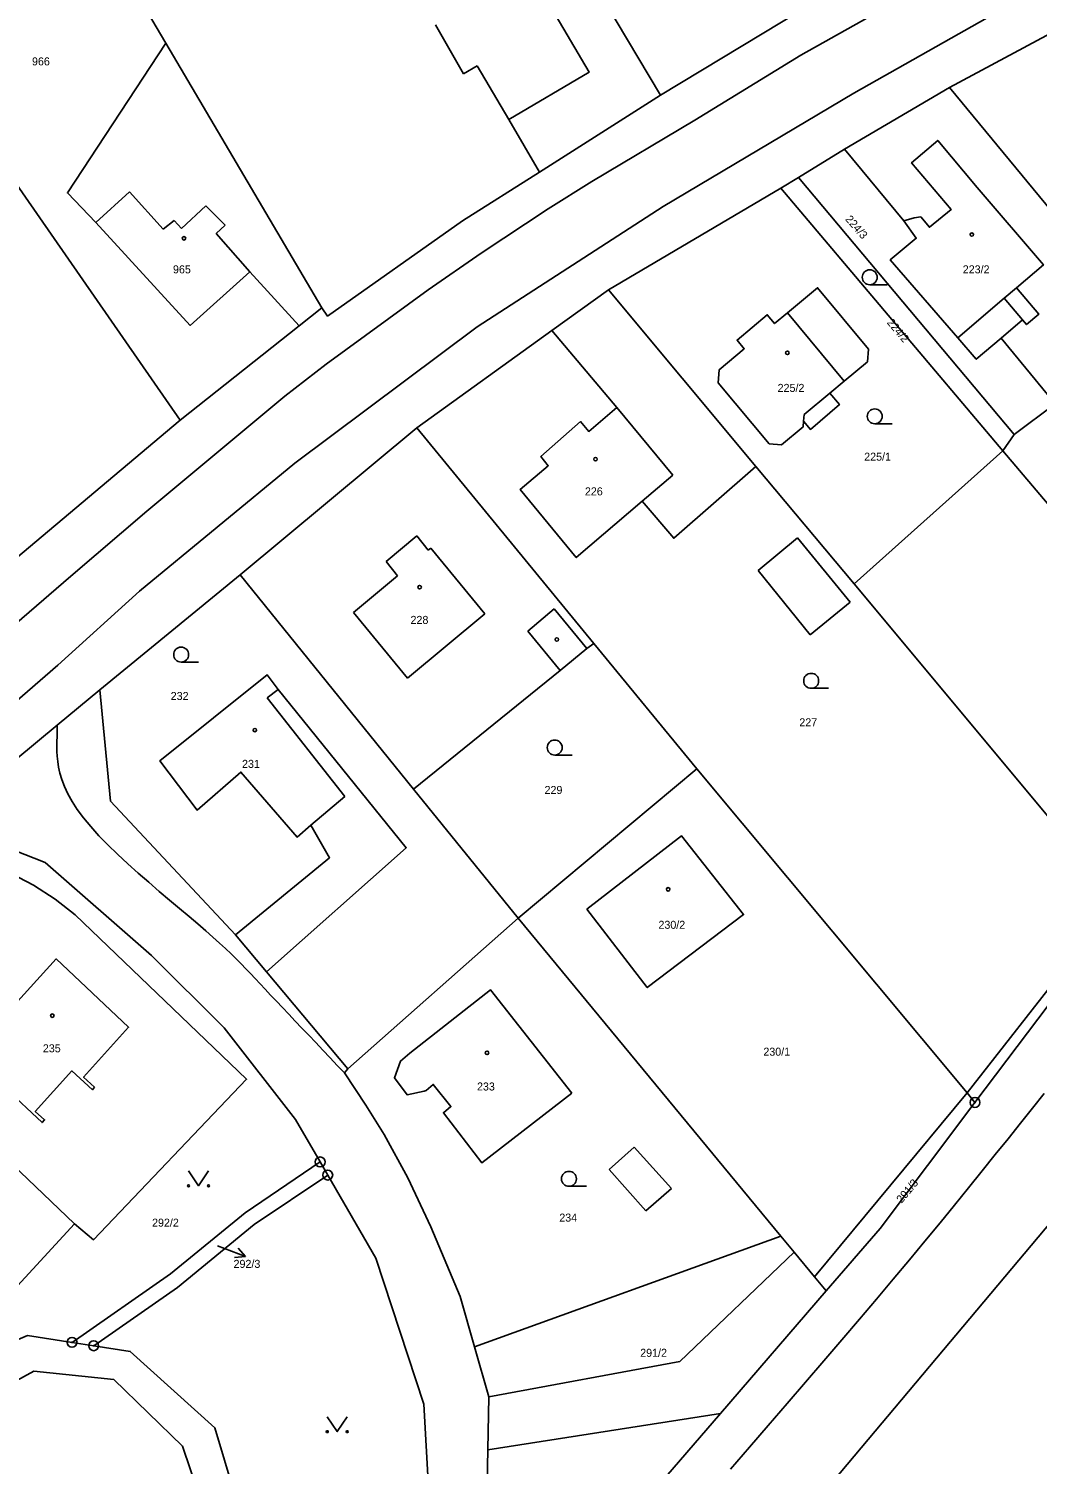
# Model space of a CAD drawing. Extents: x -587171 to -555306, y -1167727 to -1074732.
# Drawn here: x -560131.8 to -560030.6, y -1077699.8 to -1077555.8 of the extents above; entities that cross this region are included whole.
import ezdxf

# ---------------------------------------------------------------- set-up
doc = ezdxf.new("R2010")
doc.units = 0
for name, color, linetype in [('Hranice parcel', 7, 'Continuous'), ('Parcelní čísla', 7, 'Continuous'), ('Pop  PČ popisy', 7, 'Continuous'), ('Poz předměty', 7, 'Continuous'), ('Vnitřní kresba', 7, 'Continuous'), ('Značky bodu BP', 7, 'Continuous'), ('Značky budov', 7, 'Continuous'), ('Značky kultur', 7, 'Continuous')]:
    doc.layers.add(name, color=color, linetype=linetype)

msp = doc.modelspace()

# ---------------------------------------------------------------- linework, layer by layer
at = {"layer": 'Hranice parcel'}
for p, q in [((-560068.43, -1077562.5), (-560040.99, -1077545.9)), ((-560025.67, -1077554.33), (-560039.43, -1077561.72)), ((-560102.42, -1077583.81), (-560118.06, -1077557.27)), ((-560039.43, -1077561.72), (-560049.96, -1077567.9)), ((-560039.43, -1077561.72), (-559998.7, -1077611.06)), ((-560080.58, -1077570.2), (-560068.43, -1077562.5)), ((-560116.63, -1077595.08), (-560137.85, -1077564.54)), ((-560049.96, -1077567.9), (-560054.59, -1077570.74)), ((-560049.96, -1077567.9), (-560044, -1077575.1)), ((-560054.59, -1077570.74), (-560056.35, -1077571.83)), ((-560032.92, -1077596.51), (-560054.59, -1077570.74)), ((-560056.35, -1077571.83), (-560073.65, -1077582.01)), ((-560056.35, -1077571.83), (-560034.06, -1077598.15)), ((-560073.65, -1077582.01), (-560079.33, -1077586.1)), ((-560073.65, -1077582.01), (-560058.85, -1077599.73)), ((-560104.69, -1077585.61), (-560102.42, -1077583.81)), ((-560116.63, -1077595.08), (-560104.69, -1077585.61)), ((-560079.33, -1077586.1), (-560092.89, -1077595.86)), ((-560034.25, -1077586.86), (-560028.8, -1077593.44)), ((-560032.92, -1077596.51), (-560028.8, -1077593.44)), ((-560142.63, -1077616.94), (-560116.63, -1077595.08)), ((-560092.89, -1077595.86), (-560110.62, -1077610.59)), ((-560092.89, -1077595.86), (-560075.1, -1077617.48)), ((-560034.06, -1077598.15), (-560032.92, -1077596.51)), ((-560034.06, -1077598.15), (-560049, -1077611.51)), ((-560010.14, -1077626.51), (-560034.06, -1077598.15)), ((-560058.85, -1077599.73), (-560049, -1077611.51)), ((-560110.62, -1077610.59), (-560124.7, -1077622.14)), ((-560110.62, -1077610.59), (-560093.21, -1077632.08)), ((-560049, -1077611.51), (-560022.53, -1077643.23)), ((-560075.1, -1077617.48), (-560064.76, -1077630.06)), ((-560082.71, -1077645.04), (-560064.76, -1077630.06)), ((-560064.76, -1077630.06), (-560037.66, -1077662.56)), ((-560093.21, -1077632.08), (-560082.71, -1077645.04)), ((-560037.66, -1077662.56), (-560022.53, -1077643.23)), ((-560099.81, -1077660.14), (-560082.71, -1077645.04)), ((-560082.71, -1077645.04), (-560056.35, -1077676.93)), ((-560111.06, -1077646.69), (-560107.95, -1077650.41)), ((-560107.95, -1077650.41), (-560099.81, -1077660.14)), ((-560145.1, -1077658.65), (-560127.22, -1077675.7)), ((-560052.96, -1077681.02), (-560037.66, -1077662.56)), ((-560036.86, -1077663.52), (-560037.66, -1077662.56)), ((-560102.58, -1077669.49), (-560101.82, -1077670.8)), ((-560133.32, -1077682.3), (-560127.22, -1077675.7)), ((-560087.08, -1077688.03), (-560056.35, -1077676.93)), ((-560051.8, -1077682.42), (-560052.96, -1077681.02)), ((-560062.4, -1077694.71), (-560051.8, -1077682.42)), ((-560125.31, -1077687.92), (-560127.48, -1077687.58)), ((-560085.75, -1077698.36), (-560062.4, -1077694.71))]:
    msp.add_line(p, q, dxfattribs=at)
for points in [[(-560068.43, -1077562.5), (-560080.62, -1077541.99), (-560085.27, -1077534.33), (-560093.56, -1077520.46), (-560095.9, -1077516.24)], [(-560080.58, -1077570.2), (-560083.64, -1077564.92), (-560075.59, -1077560.19), (-560086.29, -1077541.98), (-560089.32, -1077543.8), (-560101.87, -1077525.59), (-560106.15, -1077527.99), (-560127.79, -1077540.53)], [(-560118.06, -1077557.27), (-560123.14, -1077548.66), (-560127.79, -1077540.53)], [(-560145.28, -1077619.37), (-560144.61, -1077619.87), (-560143.23, -1077620.49), (-560141.2, -1077620.74), (-560139.18, -1077620.34), (-560137.48, -1077619.22), (-560127.59, -1077610.74), (-560119.96, -1077604.22), (-560106.13, -1077592.68), (-560101.97, -1077589.46), (-560091.75, -1077582.02), (-560086.42, -1077578.33), (-560079.69, -1077573.89), (-560075.31, -1077571.16), (-560064.99, -1077565), (-560054.33, -1077558.48), (-560045.19, -1077553.35), (-560038.88, -1077549.66), (-560028.99, -1077543.83)], [(-560118.06, -1077557.27), (-560127.95, -1077572.29), (-560125.08, -1077575.25), (-560115.64, -1077585.58), (-560109.63, -1077580.21), (-560104.69, -1077585.61)], [(-560044, -1077575.1), (-560042.96, -1077574.79), (-560042.3, -1077574.7), (-560041.44, -1077575.74), (-560039.25, -1077573.95), (-560043.23, -1077569.27), (-560040.6, -1077567.03), (-560036.64, -1077571.74), (-560029.99, -1077579.52), (-560032.7, -1077581.82), (-560030.46, -1077584.46), (-560031.68, -1077585.49), (-560032.08, -1077585.02), (-560034.25, -1077586.86)], [(-560102.42, -1077583.81), (-560101.84, -1077584.65), (-560088.28, -1077575.08), (-560080.58, -1077570.2)], [(-560044, -1077575.1), (-560042.75, -1077576.83), (-560045.37, -1077579.01), (-560038.58, -1077586.81), (-560036.74, -1077588.98), (-560034.25, -1077586.86)], [(-560057.53, -1077597.45), (-560062.62, -1077591.34), (-560062.53, -1077590.02), (-560060.01, -1077587.92), (-560060.73, -1077587.06), (-560057.71, -1077584.51), (-560056.97, -1077585.4), (-560055.69, -1077584.33), (-560052.66, -1077581.8), (-560047.54, -1077587.97), (-560047.66, -1077589.22), (-560050, -1077591.17), (-560051.43, -1077592.36), (-560050.46, -1077593.52), (-560053.38, -1077596.01), (-560054.06, -1077595.2), (-560054.11, -1077595.76), (-560056.27, -1077597.56), (-560057.53, -1077597.45)], [(-560079.33, -1077586.1), (-560072.8, -1077593.83), (-560075.63, -1077596.22), (-560076.46, -1077595.23), (-560080.43, -1077598.72), (-560079.69, -1077599.66), (-560082.52, -1077602.05), (-560076.88, -1077608.86), (-560070.26, -1077603.22), (-560067.1, -1077606.93), (-560058.85, -1077599.73)], [(-559971.59, -1077598.43), (-560021.55, -1077666.36), (-560049.7, -1077699.85), (-560071.03, -1077725.21)], [(-560093.21, -1077632.08), (-560078.48, -1077620.21), (-560075.8, -1077618), (-560075.1, -1077617.48)], [(-560107.95, -1077650.41), (-560093.94, -1077637.98), (-560106.78, -1077622.11), (-560107.91, -1077620.62), (-560118.67, -1077629.27), (-560114.93, -1077634.19), (-560110.53, -1077630.39), (-560104.9, -1077636.9), (-560103.5, -1077635.72), (-560101.63, -1077638.97), (-560111.06, -1077646.69)], [(-560036.86, -1077663.52), (-560025.28, -1077648.17), (-560005.37, -1077620.07)], [(-560124.7, -1077622.14), (-560128.97, -1077625.67), (-560141.66, -1077636.16)], [(-560124.7, -1077622.14), (-560123.61, -1077633.31), (-560111.06, -1077646.69)], [(-560141.66, -1077636.16), (-560139.66, -1077635.74), (-560130.18, -1077639.46), (-560119.51, -1077648.78), (-560112.22, -1077656.02), (-560105.05, -1077665.22), (-560102.58, -1077669.49)], [(-560075.83, -1077644.13), (-560066.32, -1077636.77), (-560060.08, -1077644.68), (-560069.76, -1077652), (-560075.83, -1077644.13)], [(-560127.22, -1077675.7), (-560125.32, -1077677.29), (-560109.96, -1077661.19), (-560127.18, -1077644.7), (-560129.19, -1077643.14), (-560131.36, -1077641.73), (-560133.59, -1077640.57), (-560143.84, -1077639.37), (-560145.56, -1077639.39)], [(-560125.23, -1077661.98), (-560126.32, -1077660.99), (-560121.8, -1077655.97), (-560129.06, -1077649.13), (-560137.8, -1077658.71), (-560130.49, -1077665.54), (-560130.24, -1077665.26), (-560131.18, -1077664.41), (-560127.51, -1077660.36), (-560125.44, -1077662.24), (-560125.23, -1077661.98)], [(-560077.31, -1077662.58), (-560085.49, -1077652.21), (-560093.58, -1077658.59), (-560094.53, -1077659.37), (-560095.12, -1077661.04), (-560093.86, -1077662.74), (-560092.13, -1077662.39), (-560091.94, -1077662.31), (-560091.23, -1077661.71), (-560089.45, -1077663.93), (-560090.21, -1077664.56), (-560086.35, -1077669.59), (-560077.31, -1077662.58)], [(-560099.81, -1077660.14), (-560100.13, -1077660.56), (-560097.98, -1077663.78), (-560096.15, -1077666.74), (-560093.77, -1077671.09), (-560091.48, -1077675.98), (-560088.52, -1077682.97), (-560087.08, -1077688.03)], [(-560051.8, -1077682.42), (-560046.39, -1077676.15), (-560036.86, -1077663.52)], [(-560127.48, -1077687.58), (-560117.59, -1077680.72), (-560110.11, -1077674.59), (-560102.58, -1077669.49)], [(-560101.82, -1077670.8), (-560097, -1077679.13), (-560092.19, -1077693.78), (-560091.46, -1077706.32), (-560095.84, -1077716.23), (-560104.01, -1077723.44), (-560113.6, -1077725.65), (-560109.3, -1077716.95), (-560110.13, -1077706.22), (-560113.16, -1077696.17), (-560121.64, -1077688.49), (-560125.31, -1077687.92)], [(-560101.82, -1077670.8), (-560109.19, -1077675.75), (-560116.91, -1077682.08), (-560125.31, -1077687.92)], [(-560056.35, -1077676.93), (-560055.01, -1077678.55), (-560052.96, -1077681.02)], [(-560127.48, -1077687.58), (-560131.95, -1077686.88), (-560141.22, -1077690.84)], [(-560087.08, -1077688.03), (-560085.65, -1077693.03), (-560085.75, -1077698.36)], [(-560149.83, -1077713.59), (-560142.41, -1077720.45), (-560122.27, -1077724.23), (-560115.62, -1077722.09), (-560112.73, -1077716.52), (-560113.3, -1077707.19), (-560116.38, -1077697.98), (-560123.29, -1077691.3), (-560131.31, -1077690.47), (-560139.2, -1077694.8), (-560147.72, -1077704.21), (-560149.83, -1077713.59)], [(-560086.71, -1077722.08), (-560072.54, -1077706.46), (-560062.4, -1077694.71)], [(-560085.75, -1077698.36), (-560085.91, -1077706.46), (-560090.89, -1077719.2), (-560091, -1077719.3)]]:
    msp.add_lwpolyline(points, dxfattribs=at)
at = {"layer": 'Pop  PČ popisy'}
for p, q in [((-560112.87, -1077677.89), (-560110.07, -1077678.97)), ((-560110.07, -1077678.97), (-560111.18, -1077679.07)), ((-560110.07, -1077678.97), (-560110.82, -1077678.14))]:
    msp.add_line(p, q, dxfattribs=at)
at = {"layer": 'Poz předměty'}
msp.add_lwpolyline([(-560029.93, -1077662.61), (-560031.09, -1077664.08), (-560032.29, -1077665.59), (-560033.54, -1077667.16), (-560034.82, -1077668.75), (-560036.13, -1077670.39), (-560037.51, -1077672.09), (-560038.91, -1077673.82), (-560040.37, -1077675.6), (-560041.89, -1077677.44), (-560043.45, -1077679.32), (-560045.06, -1077681.25), (-560046.75, -1077683.25), (-560048.46, -1077685.27), (-560050.22, -1077687.32), (-560052.03, -1077689.44), (-560053.86, -1077691.56), (-560055.71, -1077693.71), (-560057.61, -1077695.91), (-560059.5, -1077698.1), (-560061.41, -1077700.3)], dxfattribs=at)
at = {"layer": 'Vnitřní kresba'}
for p, q in [((-560049.03, -1077562.27), (-560034.88, -1077554.31)), ((-560091.02, -1077555.43), (-560088.19, -1077560.35)), ((-560088.19, -1077560.35), (-560086.83, -1077559.56)), ((-560086.83, -1077559.56), (-560083.64, -1077564.92)), ((-560068.17, -1077573.64), (-560049.03, -1077562.27)), ((-560125.08, -1077575.25), (-560121.72, -1077572.17)), ((-560121.72, -1077572.17), (-560118.32, -1077575.94)), ((-560116.48, -1077575.86), (-560114.04, -1077573.6)), ((-560114.04, -1077573.6), (-560112.12, -1077575.54)), ((-560086.81, -1077585.73), (-560068.17, -1077573.64)), ((-560118.32, -1077575.94), (-560117.24, -1077575.05)), ((-560117.24, -1077575.05), (-560116.48, -1077575.86)), ((-560112.12, -1077575.54), (-560113.03, -1077576.35)), ((-560113.03, -1077576.35), (-560109.63, -1077580.21)), ((-560033.92, -1077582.86), (-560032.7, -1077581.82)), ((-560038.58, -1077586.81), (-560033.92, -1077582.86)), ((-560033.92, -1077582.86), (-560032.08, -1077585.02)), ((-560055.69, -1077584.33), (-560050, -1077591.17)), ((-560105.12, -1077599.39), (-560086.81, -1077585.73)), ((-560051.43, -1077592.36), (-560053.99, -1077594.5)), ((-560072.8, -1077593.83), (-560067.19, -1077600.6)), ((-560053.99, -1077594.5), (-560054.06, -1077595.2)), ((-560120.71, -1077612.25), (-560105.12, -1077599.39)), ((-560067.19, -1077600.6), (-560070.26, -1077603.22)), ((-560095.97, -1077609.27), (-560092.88, -1077606.69)), ((-560092.88, -1077606.69), (-560091.73, -1077608.14)), ((-560058.63, -1077610.17), (-560054.66, -1077606.87)), ((-560054.66, -1077606.87), (-560049.39, -1077613.33)), ((-560091.73, -1077608.14), (-560091.46, -1077607.92)), ((-560091.46, -1077607.92), (-560086.04, -1077614.51)), ((-560094.81, -1077610.7), (-560095.97, -1077609.27)), ((-560099.23, -1077614.38), (-560094.81, -1077610.7)), ((-560053.4, -1077616.6), (-560058.63, -1077610.17)), ((-560128.9, -1077619.67), (-560120.71, -1077612.25)), ((-560079.08, -1077614.01), (-560081.74, -1077616.24)), ((-560075.8, -1077618), (-560079.08, -1077614.01)), ((-560049.39, -1077613.33), (-560053.4, -1077616.6)), ((-560093.8, -1077620.96), (-560099.23, -1077614.38)), ((-560086.04, -1077614.51), (-560093.8, -1077620.96)), ((-560081.74, -1077616.24), (-560078.48, -1077620.21)), ((-560128.9, -1077619.67), (-560150.18, -1077637.96)), ((-560106.78, -1077622.11), (-560107.89, -1077622.95)), ((-560107.89, -1077622.95), (-560100.1, -1077632.83)), ((-560100.1, -1077632.83), (-560103.5, -1077635.72)), ((-560073.59, -1077670.26), (-560071.06, -1077668)), ((-560071.06, -1077668), (-560067.31, -1077672.14)), ((-560069.88, -1077674.4), (-560073.59, -1077670.26)), ((-560067.31, -1077672.14), (-560069.88, -1077674.4)), ((-560066.48, -1077689.51), (-560055.01, -1077678.55)), ((-560085.65, -1077693.03), (-560066.48, -1077689.51))]:
    msp.add_line(p, q, dxfattribs=at)
msp.add_lwpolyline([(-560128.97, -1077625.67), (-560128.97, -1077625.73), (-560128.97, -1077625.79), (-560128.98, -1077625.86), (-560128.98, -1077625.94), (-560128.98, -1077626.04), (-560128.98, -1077626.16), (-560128.98, -1077626.3), (-560128.99, -1077626.47), (-560128.99, -1077626.68), (-560128.99, -1077626.92), (-560129, -1077627.2), (-560129, -1077627.53), (-560129, -1077627.91), (-560129, -1077628.33), (-560128.97, -1077628.8), (-560128.92, -1077629.32), (-560128.83, -1077629.89), (-560128.69, -1077630.49), (-560128.49, -1077631.14), (-560128.23, -1077631.83), (-560127.9, -1077632.56), (-560127.48, -1077633.32), (-560126.96, -1077634.14), (-560126.34, -1077634.98), (-560125.61, -1077635.85), (-560124.78, -1077636.77), (-560123.88, -1077637.69), (-560122.92, -1077638.63), (-560121.89, -1077639.58), (-560120.85, -1077640.51), (-560119.79, -1077641.43), (-560118.73, -1077642.35), (-560117.69, -1077643.22), (-560116.69, -1077644.06), (-560115.74, -1077644.87), (-560114.86, -1077645.61), (-560114.06, -1077646.3), (-560113.34, -1077646.94), (-560112.68, -1077647.53), (-560112.08, -1077648.08), (-560111.52, -1077648.62), (-560111.01, -1077649.12), (-560110.52, -1077649.61), (-560110.04, -1077650.11), (-560109.57, -1077650.6), (-560109.09, -1077651.1), (-560108.6, -1077651.62), (-560108.09, -1077652.17), (-560107.55, -1077652.75), (-560106.97, -1077653.36), (-560106.37, -1077654), (-560105.74, -1077654.66), (-560105.08, -1077655.35), (-560104.42, -1077656.06), (-560103.73, -1077656.78), (-560103.02, -1077657.52), (-560102.31, -1077658.27), (-560101.59, -1077659.03), (-560100.86, -1077659.8), (-560100.13, -1077660.56)], dxfattribs=at)
at = {"layer": 'Značky bodu BP'}
for centre, radius in [((-560036.86, -1077663.52), 0.5), ((-560036.86, -1077663.52), 0.0303), ((-560102.58, -1077669.49), 0.5), ((-560102.58, -1077669.49), 0.0303), ((-560101.82, -1077670.8), 0.5), ((-560101.82, -1077670.8), 0.0303), ((-560127.48, -1077687.58), 0.5), ((-560127.48, -1077687.58), 0.0303), ((-560125.31, -1077687.92), 0.5), ((-560125.31, -1077687.92), 0.0303)]:
    msp.add_circle(centre, radius, dxfattribs=at)
at = {"layer": 'Značky budov'}
for centre in [(-560116.25, -1077576.84), (-560037.18, -1077576.47), (-560055.69, -1077588.33), (-560074.94, -1077599), (-560092.6, -1077611.83), (-560078.83, -1077617.09), (-560109.13, -1077626.17), (-560067.66, -1077642.14), (-560129.46, -1077654.81), (-560085.83, -1077658.54)]:
    msp.add_circle(centre, 0.175, dxfattribs=at)
at = {"layer": 'Značky kultur'}
for p, q in [((-560047.42, -1077581.5), (-560045.67, -1077581.5)), ((-560046.92, -1077595.45), (-560045.17, -1077595.45)), ((-560116.53, -1077619.35), (-560114.78, -1077619.35)), ((-560053.3, -1077621.98), (-560051.55, -1077621.98)), ((-560079.04, -1077628.67), (-560077.29, -1077628.67)), ((-560077.61, -1077671.93), (-560075.86, -1077671.93))]:
    msp.add_line(p, q, dxfattribs=at)
for points in [[(-560115.78, -1077670.37), (-560114.78, -1077671.87), (-560113.78, -1077670.37)], [(-560101.86, -1077695.04), (-560100.86, -1077696.54), (-560099.86, -1077695.04)]]:
    msp.add_lwpolyline(points, dxfattribs=at)
for centre, radius in [((-560047.42, -1077580.75), 0.75), ((-560046.92, -1077594.7), 0.75), ((-560116.53, -1077618.6), 0.75), ((-560053.3, -1077621.23), 0.75), ((-560079.04, -1077627.92), 0.75), ((-560115.78, -1077671.87), 0.1), ((-560113.78, -1077671.87), 0.1), ((-560077.61, -1077671.18), 0.75), ((-560101.86, -1077696.54), 0.1), ((-560099.86, -1077696.54), 0.1)]:
    msp.add_circle(centre, radius, dxfattribs=at)

# ---------------------------------------------------------------- texts
at = {"layer": 'Parcelní čísla'}
for s, p in [('966', (-560131.5, -1077559.5)), ('965', (-560117.35, -1077580.36)), ('223/2', (-560038.09, -1077580.36)), ('225/2', (-560056.67, -1077592.25)), ('225/1', (-560047.98, -1077599.15)), ('226', (-560076.01, -1077602.63)), ('228', (-560093.51, -1077615.52)), ('232', (-560117.58, -1077623.15)), ('227', (-560054.49, -1077625.79)), ('231', (-560110.42, -1077629.96)), ('229', (-560080.06, -1077632.58)), ('230/2', (-560068.63, -1077646.1)), ('235', (-560130.41, -1077658.49)), ('230/1', (-560058.1, -1077658.83)), ('233', (-560086.84, -1077662.32)), ('234', (-560078.58, -1077675.47)), ('292/2', (-560119.45, -1077675.98)), ('292/3', (-560111.27, -1077680.11)), ('291/2', (-560070.46, -1077689.03))]:
    msp.add_text(s, height=0.803, dxfattribs=at).set_placement(p)
for s, rotation, p in [('224/3', 311, (-560049.93, -1077574.96)), ('224/2', 310, (-560045.75, -1077585.32)), ('291/3', 50, (-560044.22, -1077673.68))]:
    msp.add_text(s, height=0.803, rotation=rotation, dxfattribs=at).set_placement(p)

doc.saveas('drawing.dxf')
